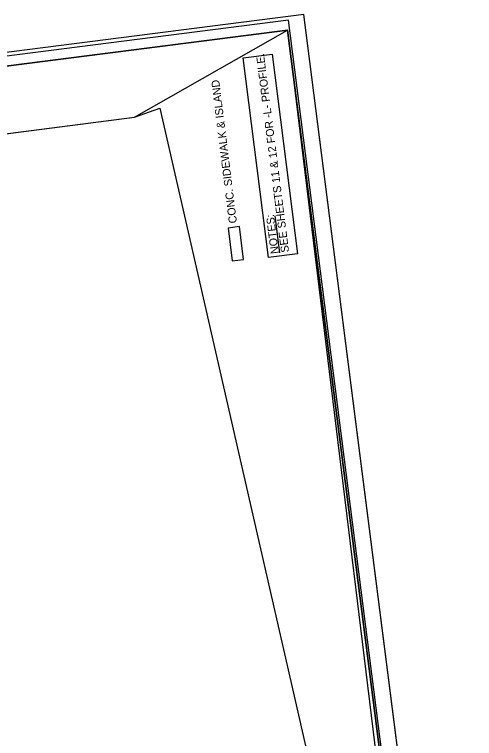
# Model space of a CAD drawing. Extents: x 2367861 to 2369161, y 805913 to 807722.
# Drawn here: x 2368586 to 2369161, y 806817 to 807722 of the extents above; entities that cross this region are included whole.
import ezdxf

# ---------------------------------------------------------------- set-up
doc = ezdxf.new("R2010")
doc.units = 0
for name, color, linetype in [('Old_Level_10', 7, 'Continuous'), ('Old_Level_15', 7, 'Continuous'), ('Old_Level_22', 7, 'Continuous'), ('Old_Level_4', 7, 'Continuous'), ('Old_Level_5', 7, 'Continuous'), ('Old_Level_6', 7, 'Continuous'), ('Old_Level_62', 7, 'Continuous'), ('Old_Level_9', 7, 'Continuous'), ('Plot Label CELL', 7, 'Continuous'), ('Plot Shape CELL', 7, 'Continuous')]:
    doc.layers.add(name, color=color, linetype=linetype)

msp = doc.modelspace()

# ---------------------------------------------------------------- linework, layer by layer
at = {"layer": 'Old_Level_10'}
msp.add_lwpolyline([(2368075.8, 806080.82), (2369117.31, 806213.86), (2368927.28, 807701.78), (2368095.52, 807595.55), (2368125.83, 807358.22), (2367916.05, 807331.43)], close=True, dxfattribs=at)
at = {"layer": 'Old_Level_15'}
msp.add_line((2369160.73, 806051.57), (2368947.45, 807721.5), dxfattribs=at)
at = {"layer": 'Old_Level_22'}
for points in [[(2367911.07, 807370.33), (2368083.23, 807392.33), (2368175.69, 807520.89), (2368735.93, 807593.18), (2368927.27, 807701.79), (2369092.24, 806348.18), (2368949.93, 806267.04), (2368854.97, 806248.12), (2368355.62, 806182.14), (2368067.12, 806148.73)], [(2367911.07, 807370.33), (2368083.23, 807392.33), (2368175.69, 807520.89), (2368735.93, 807593.18), (2368767.44, 807604.56), (2369060.29, 806323.24), (2368949.93, 806267.04), (2368854.97, 806248.12), (2368355.62, 806182.14), (2368067.12, 806148.73)]]:
    msp.add_lwpolyline(points, close=True, dxfattribs=at)
at = {"layer": 'Old_Level_4'}
msp.add_lwpolyline([(2369139.25, 806061.93), (2368928.17, 807714.49), (2367881.68, 807580.85), (2368092.75, 805928.27)], close=True, dxfattribs=at)
at = {"layer": 'Old_Level_5'}
msp.add_lwpolyline([(2368872.2, 807415.55), (2368867.09, 807456.56), (2368852.93, 807454.79), (2368858.04, 807413.78), (2368872.2, 807415.55)], dxfattribs=at)
at = {"layer": 'Old_Level_6'}
msp.add_lwpolyline([(2369160.73, 806051.57), (2368947.45, 807721.5), (2367861.28, 807582.78), (2368074.56, 805912.84)], close=True, dxfattribs=at)
at = {"layer": 'Old_Level_62'}
msp.add_line((2368175.69, 807520.89), (2368735.93, 807593.18), dxfattribs=at)
at = {"layer": 'Old_Level_9'}
msp.add_lwpolyline([(2368872.2, 807415.55), (2368867.09, 807456.56), (2368852.93, 807454.79), (2368858.04, 807413.78), (2368872.2, 807415.55)], dxfattribs=at)
at = {"layer": 'Plot Label CELL'}
msp.add_line((2368917.34, 807423.7), (2368911.49, 807469.82), dxfattribs=at)
msp.add_lwpolyline([(2368903.5, 807417.78), (2368871.64, 807667.29), (2368907.85, 807671.91), (2368939.72, 807422.4)], close=True, dxfattribs=at)
at = {"layer": 'Plot Shape CELL'}
for points in [[(2367885.73, 807568.79), (2368075.77, 806080.84), (2369117.31, 806213.86), (2368927.27, 807701.79)], [(2369117.31, 806213.86), (2368075.8, 806080.82), (2367911.07, 807370.33), (2368059.92, 807389.35), (2368034.59, 807587.78), (2368927.27, 807701.79)]]:
    msp.add_lwpolyline(points, close=True, dxfattribs=at)

# ---------------------------------------------------------------- texts
at = {"layer": 'Plot Label CELL'}
for s, rotation, p in [('SEE SHEETS 11 & 12 FOR -L- PROFILE.', 97.22897, (2368929.06, 807424.86)), ('CONC. SIDEWALK & ISLAND', 97.10772, (2368863.95, 807461.26)), ('NOTES:', 97.22897, (2368916.22, 807423.08))]:
    msp.add_text(s, height=10, rotation=rotation, dxfattribs=at).set_placement(p)

doc.saveas('drawing.dxf')
